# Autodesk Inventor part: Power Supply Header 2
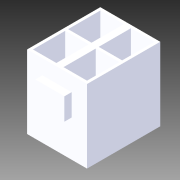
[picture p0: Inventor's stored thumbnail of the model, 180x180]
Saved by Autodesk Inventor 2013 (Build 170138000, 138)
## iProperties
Company: Autodesk Inc.
Created: 2005-12
Part Number: Power Supply Header 2
Document SubType Name: Modeling
Designer: Autodesk Inc.
Density: 1 g/cm^3
Mass: 0.43596 g
Surface Area: 9.6688 cm^2
Volume: 0.43596 cm^3
Material: Allgemein
Title: Personal Computer
Author: Autodesk Inc.
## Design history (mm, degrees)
sketch "Sketch1"
  geometry: L1 (0, 7)-(0, -7) reference; L2 (-5.727, 0)-(5.727, 0) reference; L3 (-4.091, 5)-(4.091, 5); L4 (4.091, 5)-(4.091, -5); L5 (4.091, -5)-(-4.091, -5); L6 (-4.091, -5)-(-4.091, 5)
  constraints: 8 end point, 2 parallel, 1 horizontal, 1 perpendicular, 2 other
  dimensions: "d0" = 8.182 distance of L3.start L3.end; "d1" = 10 distance of L5.end L3.start
extrude "Extrusion1" new body sketch "Sketch1" distance "d2" = 10; taper "d3" = 0 deg
sketch "Sketch5"
  geometry: L1 (8.182, 10)-(0, 10); L2 (2.091, 8)-(6.091, 8); L3 (6.091, 8)-(6.091, 5); L4 (6.091, 5)-(2.091, 5); L5 (2.091, 5)-(2.091, 8); 2 further points
  constraints: 10 end point, 2 midpoint, 2 parallel, 1 horizontal, 1 perpendicular, 1 vertical alignment
  dimensions: "d20" = 4 distance of L3.end L4.end; "d21" = 3 distance of L2.end L3.end; "d22" = 2 distance between parallel lines of L1 L2
extrude "Extrusion5" join sketch "Sketch5" distance "d23" = 1; taper "d24" = 0 deg
workplane "Work Plane1"
sketch "Sketch11"
  geometry: L1 (-0.491, -4.6)-(-3.691, -4.6); L2 (-3.691, -4.6)-(-3.691, -0.2); L3 (-3.691, -0.2)-(-0.491, -0.2); L4 (-0.491, -0.2)-(-0.491, -4.6); L5 (-4.091, -5)-(-4.091, 5) reference; L6 (4.091, -5)-(-4.091, -5) reference
  constraints: 8 end point, 2 parallel, 1 horizontal, 1 perpendicular
  dimensions: "d57" = 0.4 distance between parallel lines of L6 L1; "d58" = 0.4 distance between parallel lines of L5 L2; "d59" = 3.2 distance of L2.end L3.end; "d60" = 4.4 distance of L3.end L1.start
extrude "Extrusion11" cut sketch "Sketch11" distance "d49" = 7; taper "d50" = 0 deg
pattern_linear "Rectangular Pattern3" dims "d53" = 4.182, "d56" = 4.8
body "Solid1"
other parameters: "d4" = 0
